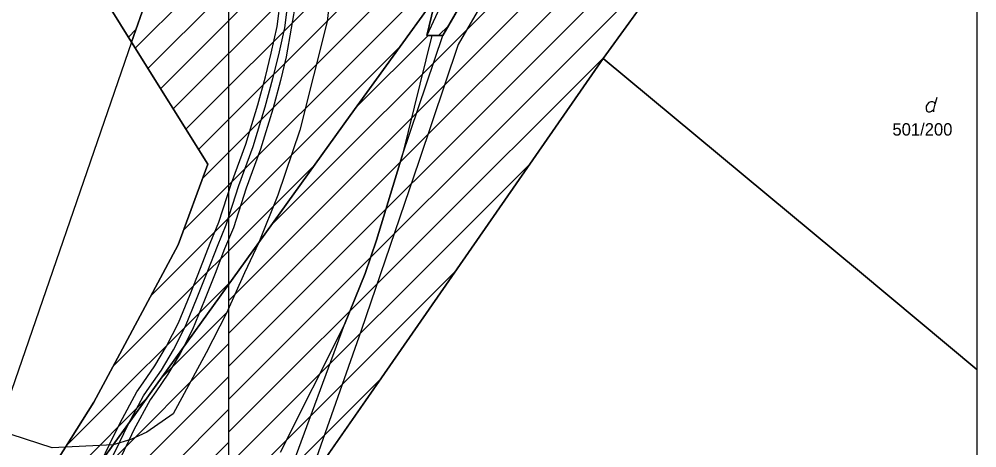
# Model space of a CAD drawing. Extents: x -264309 to -263505, y -1242443 to -1241763.
# Drawn here: x -263712.8 to -263589.3, y -1242146.2 to -1242090.9 of the extents above; entities that cross this region are included whole.
import ezdxf

# ---------------------------------------------------------------- set-up
doc = ezdxf.new("R2010")
doc.units = 0
for name, color, linetype in [('KN_2019_08_16', 7, 'Continuous'), ('KN_2019_08_16_KLADPAR', 7, 'Continuous'), ('KN_2019_08_16_ZAPPAR', 7, 'Continuous'), ('RAM_NA_TLAC_10xA4_1-500', 7, 'Continuous'), ('SRAFY_PARCELY', 7, 'Continuous')]:
    doc.layers.add(name, color=color, linetype=linetype)

msp = doc.modelspace()

# ---------------------------------------------------------------- linework, layer by layer
at = {"layer": 'KN_2019_08_16'}
for p, q in [((-263658.2, -1242093.02), (-263653.54, -1242084.98)), ((-263651.55, -1242086.13), (-263656.21, -1242094.17)), ((-263663.45, -1242108.53), (-263658.2, -1242093.02)), ((-263656.21, -1242094.17), (-263661.27, -1242109.27)), ((-263661.27, -1242109.27), (-263668.72, -1242131.08)), ((-263666.73, -1242119.41), (-263663.45, -1242108.53)), ((-263668.23, -1242123.7), (-263666.73, -1242119.41)), ((-263670.89, -1242130.32), (-263668.23, -1242123.7)), ((-263678.53, -1242150.99), (-263670.89, -1242130.32)), ((-263668.72, -1242131.08), (-263675.77, -1242151.07))]:
    msp.add_line(p, q, dxfattribs=at)
for points in [[(-263658.83, -1242004.48), (-263660.39, -1242010.9), (-263662.24, -1242017.89), (-263665.58, -1242030.48), (-263670.06, -1242043.75), (-263671.09, -1242047.37), (-263671.92, -1242051.25), (-263676.48, -1242072.53), (-263676.59, -1242073.05), (-263677, -1242074.16), (-263676.93, -1242075.39), (-263676.49, -1242078.07), (-263676.63, -1242082.51), (-263677.1, -1242088.32), (-263678.38, -1242095.75), (-263679.14, -1242098.82), (-263680.13, -1242102.51)], [(-263709.17, -1242164.6), (-263699.96, -1242145.6), (-263698.75, -1242143.11), (-263696.8, -1242139.5), (-263696.02, -1242138.4), (-263694.49, -1242136.18), (-263692.95, -1242133.56), (-263691.37, -1242130.51), (-263689.86, -1242126.8), (-263688.5, -1242123.37), (-263687.27, -1242120.18), (-263686.13, -1242117.46), (-263684.49, -1242112.38), (-263682.66, -1242107.34), (-263681.09, -1242102.23), (-263680.11, -1242098.57), (-263679.35, -1242095.52), (-263678.56, -1242092.03), (-263678.1, -1242088.22)], [(-263702.21, -1242147.92), (-263701.21, -1242145.86), (-263699.82, -1242142.99), (-263697.65, -1242138.97), (-263696.84, -1242137.83), (-263695.33, -1242135.64), (-263693.83, -1242133.08), (-263692.28, -1242130.09), (-263690.79, -1242126.43), (-263689.43, -1242123.01), (-263688.2, -1242119.81), (-263687.07, -1242117.11), (-263685.44, -1242112.06), (-263683.61, -1242107.02), (-263682.05, -1242101.95), (-263681.08, -1242098.32), (-263680.32, -1242095.29), (-263679.55, -1242091.86), (-263679.1, -1242088.12)], [(-263680.13, -1242102.51), (-263681.71, -1242107.66), (-263683.54, -1242112.7), (-263685.19, -1242117.81), (-263686.34, -1242120.55), (-263687.57, -1242123.73), (-263688.93, -1242127.17), (-263690.46, -1242130.93), (-263691.69, -1242133.3), (-263692.07, -1242134.04), (-263693.65, -1242136.72), (-263695.2, -1242138.97), (-263695.95, -1242140.03), (-263698.04, -1242143.91), (-263698.67, -1242145.2), (-263708.3, -1242165.09)]]:
    msp.add_lwpolyline(points, dxfattribs=at)
at = {"layer": 'KN_2019_08_16_KLADPAR'}
for p, q in [((-263634.2, -1242091.43), (-263619.25, -1242070.54)), ((-263589.31, -1242086.21), (-263589.31, -1242136.09)), ((-263637.5, -1242095.97), (-263634.2, -1242091.43)), ((-263666.12, -1242137.18), (-263637.5, -1242095.97)), ((-263604.45, -1242123.47), (-263637.5, -1242095.97)), ((-263637.5, -1242095.97), (-263604.45, -1242123.47)), ((-263594.7, -1242101.85), (-263594.43, -1242100.95)), ((-263589.31, -1242136.09), (-263604.45, -1242123.47)), ((-263604.45, -1242123.47), (-263589.31, -1242136.09)), ((-263589.31, -1242136.09), (-263589.31, -1242158.57)), ((-263678.83, -1242155.48), (-263666.12, -1242137.18))]:
    msp.add_line(p, q, dxfattribs=at)
for points in [[(-263659.07, -1242087.95), (-263656.62, -1242077.85), (-263653.93, -1242064.92), (-263651.67, -1242053.72), (-263651.18, -1242056.5), (-263650.46, -1242060.65), (-263646.65, -1242064.99), (-263643.45, -1242066.48), (-263643.2, -1242066.6), (-263638.63, -1242066.92), (-263630.05, -1242064.33), (-263619.73, -1242060.13), (-263606.95, -1242052.98), (-263617.25, -1242067.34), (-263619.25, -1242070.54), (-263624.38, -1242072.67), (-263632.29, -1242075.94), (-263639.58, -1242078.41), (-263648.01, -1242081.25), (-263652.34, -1242083.75), (-263653.54, -1242084.98), (-263658.2, -1242093.02), (-263659.63, -1242093.02), (-263660.26, -1242093.02)], [(-263766.58, -1242082.89), (-263701.19, -1242089.29), (-263698.34, -1242093.87), (-263688.51, -1242109.63), (-263692.31, -1242120.01), (-263699.84, -1242134.09), (-263703.22, -1242140.34), (-263706.87, -1242146.12), (-263713.18, -1242156.13), (-263748.89, -1242212.77), (-263757.19, -1242207.25), (-263758.42, -1242206.43), (-263766.58, -1242201.01), (-263766.58, -1242144.85), (-263766.58, -1242122.39), (-263766.58, -1242113.95), (-263766.58, -1242093.5)]]:
    msp.add_lwpolyline(points, close=True, dxfattribs=at)
for points in [[(-263801.28, -1242075.1), (-263785.17, -1242077.19), (-263784.12, -1242072.3), (-263781.45, -1242072.38), (-263780.92, -1242070.3), (-263775.63, -1242071.05), (-263775.43, -1242063.83), (-263782.64, -1242063.41), (-263782.02, -1242058.63), (-263736.68, -1242063.45), (-263689.5, -1242068.4), (-263696.42, -1242088.33), (-263698.34, -1242093.87), (-263701.19, -1242089.29), (-263766.58, -1242082.89), (-263766.58, -1242093.5), (-263766.58, -1242113.95), (-263766.58, -1242122.39), (-263766.58, -1242144.85), (-263804.58, -1242145.58)], [(-263711.04, -1242160.22), (-263700.71, -1242145.84), (-263697.71, -1242141.67), (-263681.94, -1242119.74), (-263670.14, -1242103.34), (-263659.07, -1242087.95), (-263660.26, -1242093.02), (-263659.63, -1242093.02), (-263658.2, -1242093.02), (-263653.54, -1242084.98), (-263652.34, -1242083.75), (-263648.01, -1242081.25), (-263639.58, -1242078.41), (-263632.29, -1242075.94), (-263624.38, -1242072.67), (-263619.25, -1242070.54), (-263634.2, -1242091.43), (-263637.5, -1242095.97), (-263666.12, -1242137.18), (-263678.83, -1242155.48)], [(-263713.18, -1242156.13), (-263706.87, -1242146.12), (-263703.22, -1242140.34), (-263699.84, -1242134.09), (-263692.31, -1242120.01), (-263688.51, -1242109.63), (-263698.34, -1242093.87), (-263696.42, -1242088.33)], [(-263659.07, -1242087.95), (-263670.14, -1242103.34), (-263681.94, -1242119.74), (-263697.71, -1242141.67), (-263700.71, -1242145.84), (-263711.04, -1242160.22)], [(-263594.88, -1242102.84), (-263594.88, -1242102.57), (-263594.7, -1242101.85), (-263594.79, -1242101.67), (-263594.97, -1242101.58), (-263595.24, -1242101.58), (-263595.51, -1242101.67), (-263595.69, -1242101.85), (-263595.87, -1242102.12), (-263595.87, -1242102.48), (-263595.78, -1242102.75), (-263595.6, -1242102.84), (-263595.33, -1242102.84), (-263595.15, -1242102.75), (-263594.88, -1242102.57)]]:
    msp.add_lwpolyline(points, dxfattribs=at)
at = {"layer": 'KN_2019_08_16_ZAPPAR'}
for p, q in [((-263673.09, -1242091.19), (-263676.64, -1242105.23)), ((-263670.89, -1242130.32), (-263679.16, -1242146.82)), ((-263688.73, -1242133.94), (-263692.97, -1242141.82)), ((-263700.71, -1242145.84), (-263706.87, -1242146.12))]:
    msp.add_line(p, q, dxfattribs=at)
for points in [[(-263641.41, -1242076.9), (-263644.77, -1242078.04), (-263650.02, -1242080.28), (-263654.27, -1242083.02), (-263656.75, -1242085.95), (-263658.33, -1242088.82), (-263660.26, -1242093.02)], [(-263672.35, -1242083.11), (-263672.36, -1242084.58), (-263673.09, -1242091.19)], [(-263659.63, -1242093.02), (-263663.45, -1242108.53), (-263666.73, -1242119.41), (-263668.23, -1242123.7), (-263670.89, -1242130.32)], [(-263698.34, -1242093.87), (-263715.64, -1242143.92), (-263719.68, -1242150.03), (-263738.33, -1242178.96)], [(-263676.64, -1242105.23), (-263679.47, -1242113.61), (-263681.94, -1242119.74)], [(-263681.94, -1242119.74), (-263683.76, -1242123.64), (-263686.08, -1242128.86), (-263688.73, -1242133.94)], [(-263692.97, -1242141.82), (-263696.37, -1242144.18), (-263698.44, -1242145.13), (-263700.71, -1242145.84)], [(-263706.87, -1242146.12), (-263708.6, -1242146.2), (-263715.64, -1242143.92)]]:
    msp.add_lwpolyline(points, dxfattribs=at)
at = {"layer": 'RAM_NA_TLAC_10xA4_1-500'}
msp.add_lwpolyline([(-264210.83, -1242050.54), (-264105.83, -1242050.54), (-264000.83, -1242050.54), (-263895.83, -1242050.54), (-263790.83, -1242050.54), (-263685.83, -1242050.54), (-263685.83, -1242199.04), (-263685.83, -1242347.54), (-263790.83, -1242347.54), (-263895.83, -1242347.54), (-264000.83, -1242347.54), (-264105.83, -1242347.54), (-264210.83, -1242347.54), (-264210.83, -1242199.04)], close=True, dxfattribs=at)
at = {"layer": 'SRAFY_PARCELY'}
for p, q in [((-263691.34, -1242105.09), (-263654.66, -1242068.41)), ((-263685.83, -1242135.72), (-263621.63, -1242071.53)), ((-263697.86, -1242094.64), (-263676.1, -1242072.89)), ((-263689.71, -1242107.71), (-263655.77, -1242073.77)), ((-263685.83, -1242131.48), (-263628.87, -1242074.53)), ((-263696.23, -1242097.26), (-263674.32, -1242075.35)), ((-263685.83, -1242127.24), (-263635.68, -1242077.09)), ((-263694.6, -1242099.87), (-263673.16, -1242078.43)), ((-263689.16, -1242111.4), (-263656.94, -1242079.18)), ((-263680.32, -1242117.49), (-263642.09, -1242079.25)), ((-263685.83, -1242139.96), (-263626.42, -1242080.56)), ((-263692.97, -1242102.48), (-263672.75, -1242082.26)), ((-263691.61, -1242118.09), (-263658.3, -1242084.79)), ((-263698.75, -1242093.21), (-263697.77, -1242092.23)), ((-263658.74, -1242093.02), (-263657.46, -1242091.74)), ((-263669.44, -1242102.36), (-263660.09, -1242093.02)), ((-263695.79, -1242126.51), (-263663.8, -1242094.53)), ((-263685.83, -1242144.21), (-263637.26, -1242095.65)), ((-263700.69, -1242135.65), (-263674.68, -1242109.64)), ((-263685.83, -1242148.45), (-263646.94, -1242109.57)), ((-263685.83, -1242152.69), (-263656.59, -1242123.45)), ((-263706.8, -1242146.01), (-263685.55, -1242124.76)), ((-263694.56, -1242137.29), (-263685.83, -1242128.55)), ((-263705.41, -1242152.38), (-263685.83, -1242132.8)), ((-263716.41, -1242167.63), (-263685.83, -1242137.04)), ((-263685.83, -1242156.93), (-263666.23, -1242137.34)), ((-263714.04, -1242157.49), (-263696.41, -1242139.87)), ((-263727.57, -1242183.03), (-263685.83, -1242141.28)), ((-263738.58, -1242198.28), (-263685.83, -1242145.52))]:
    msp.add_line(p, q, dxfattribs=at)

# ---------------------------------------------------------------- texts
at = {"layer": 'KN_2019_08_16_KLADPAR'}
msp.add_text('501/200', height=1.6, dxfattribs=at).set_placement((-263600.2, -1242105.92))

doc.saveas('drawing.dxf')
